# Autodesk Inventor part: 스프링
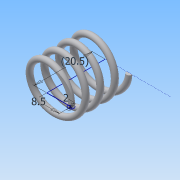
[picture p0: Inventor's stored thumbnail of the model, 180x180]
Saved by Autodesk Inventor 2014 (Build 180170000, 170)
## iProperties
Created: 2017-07
Part Number: 스프링
Material: Generic
Document SubType Name: Modeling
Designer: user
Density: 1 g/cm^3
Appearance: Default
Mass: 0.657231 g
Surface Area: 13.3943 cm^2
Volume: 0.657231 cm^3
Author: user
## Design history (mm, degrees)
sketch "스케치1"
  geometry: L1 (8.5, 0)-(0, 0); L2 (0, 0)-(0, 20.5); L3 (0, 20.5)-(22.973, 20.5); C1 r 1 at (8.5, 0)
  constraints: 6 end point, 2 perpendicular, 1 centre point, 1 coincident, 1 horizontal
  dimensions: "d0" = 20.5 distance of L1.end L2.end (derived); "d1" = 8.5 distance of L1.start L1.end; "d2" = 2 diameter of C1
feature "코일1" sketch "스케치1" pitch "d3" = 10; turns "d5" = 4; dims "d4" = 20.49994 (computed from d0), "d6" = 0, angle "d7" = 90 deg, angle "d8" = 90 deg, "d9" = 0, "d10" = 0
node "작업 평면1"
sketch "스케치2"
  geometry: L1 (-9.5, 0)-(-7.5, 0) reference; L2 (-9.5, 0)-(-7.5, 0) reference; 1 further point
  constraints: 2 horizontal alignment
extrude "돌출1" cut sketch "스케치2" distance "d11" = 10; taper "d12" = 0 deg
node "작업 평면2"
sketch "스케치3"
  geometry: L1 (-7.5, 0)-(-9.5, 0) reference; 1 further point
  constraints: 1 horizontal alignment
extrude "돌출2" cut sketch "스케치3" distance "d13" = 10; taper "d14" = 0 deg
node "솔리드1"
node "절단 모서리 투영1"
node "절단 모서리 투영2"
node "절단 모서리 투영3"
